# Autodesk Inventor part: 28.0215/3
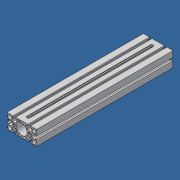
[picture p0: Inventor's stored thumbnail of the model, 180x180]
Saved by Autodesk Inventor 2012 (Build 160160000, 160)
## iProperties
Created: 2011-05
Part Number: 28.0215/3
Material: Aluminum-6061
Description: L = TRAVEL + 4.331", MILL TO 28.0215/3
Document SubType Name: Modeling
Designer: Administrator
Stock Number: 20.1017 PROFILE 45X90 S
Density: 2.71 g/cm^3
Vendor: F
FINISH: CLEAR ANODIZED
Author: Administrator
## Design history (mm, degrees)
sketch "Sketch1"
  geometry: L1 (11.7, 20.5)-(11.7, 15.701) reference; L2 (-11.7, 15.701)-(-11.7, 20.5) reference; L3 (-11.7, 20.5)-(11.7, 20.5) reference; L4 (-11.7, -20.5)-(-11.7, -15.701) reference; L5 (11.7, -15.701)-(11.7, -20.5) reference; L6 (11.7, -20.5)-(-11.7, -20.5) reference; L7 (26.6, 22.5)-(26.6, 18) reference; L8 (27.1, 18)-(29.3, 18) reference; L9 (29.3, 18)-(29.3, 9.5) reference; L10 (29.3, 9.5)-(27, 7.2) reference; L11 (27, 7.2)-(18, 7.2) reference; L12 (18, 7.2)-(15.7, 9.5) reference; L13 (15.7, 9.5)-(15.7, 18) reference; L14 (18.4, 18)-(18.4, 22.5) reference; L15 (-18.4, 22.5)-(-18.4, 18) reference; L16 (-15.7, 18)-(-15.7, 9.5) reference; L17 (-15.7, 9.5)-(-18, 7.2) reference; L18 (-18, 7.2)-(-27, 7.2) reference; L19 (-27, 7.2)-(-29.3, 9.5) reference; L20 (-29.3, 9.5)-(-29.3, 18) reference; L21 (-29.3, 18)-(-27.1, 18) reference; L22 (-26.6, 18)-(-26.6, 22.5) reference; L23 (-45, 4.1)-(-40.5, 4.1) reference; L24 (-40.5, 6.8)-(-32, 6.8) reference; L25 (-32, 6.8)-(-29.7, 4.5) reference; L26 (-29.7, 4.5)-(-29.7, -4.5) reference; L27 (-29.7, -4.5)-(-32, -6.8) reference; L28 (-32, -6.8)-(-40.5, -6.8) reference; L29 (-40.5, -6.8)-(-40.5, -4.6) reference; L30 (-40.5, -4.1)-(-45, -4.1) reference; L31 (-45, -22.5)-(-45, -4.4) reference; L32 (-26.6, -22.5)-(-26.6, -18) reference; L33 (-27.1, -18)-(-29.3, -18) reference; L34 (-29.3, -18)-(-29.3, -9.5) reference; L35 (-29.3, -9.5)-(-27, -7.2) reference; L36 (-27, -7.2)-(-18, -7.2) reference; L37 (-18, -7.2)-(-15.7, -9.5) reference; L38 (-15.7, -9.5)-(-15.7, -18) reference; L39 (-18.4, -18)-(-18.4, -22.5) reference; L40 (18.4, -22.5)-(18.4, -18) reference; L41 (15.7, -18)-(15.7, -9.5) reference; L42 (15.7, -9.5)-(18, -7.2) reference; L43 (18, -7.2)-(27, -7.2) reference; L44 (27, -7.2)-(29.3, -9.5) reference; L45 (29.3, -9.5)-(29.3, -18) reference; L46 (29.3, -18)-(27.1, -18) reference; L47 (26.6, -18)-(26.6, -22.5) reference; L48 (45, -22.5)-(26.9, -22.5) reference; L49 (45, -4.4)-(45, -22.5) reference; L50 (45, -4.1)-(40.5, -4.1) reference; L51 (40.5, -4.6)-(40.5, -6.8) reference; L52 (40.5, -6.8)-(32, -6.8) reference; L53 (32, -6.8)-(29.7, -4.5) reference; L54 (29.7, -4.5)-(29.7, 4.5) reference; L55 (29.7, 4.5)-(32, 6.8) reference; L56 (32, 6.8)-(40.5, 6.8) reference; L57 (40.5, 4.1)-(45, 4.1) reference; L58 (26.9, 22.5)-(45, 22.5) reference; L59 (-45, -4.4)-(-45, -4.1) reference; L60 (-45, 4.1)-(-45, 22.5) reference; L61 (-40.5, -4.6)-(-40.5, -4.1) reference; L62 (-40.5, 4.1)-(-40.5, 6.8) reference; L63 (-27.1, 18)-(-26.6, 18) reference; L64 (-18.4, 18)-(-15.7, 18) reference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; C1 r 3.75 at (22.5, 0) reference; C2 r 3.75 at (-22.5, 0) reference; C3 r 16 at (0, 0) reference; C4 r 5.85 at (-37.15, -14.65) reference; C5 r 5.85 at (-37.15, 14.65) reference; C6 r 5.85 at (37.15, -14.65) reference; C7 r 5.85 at (37.15, 14.65) reference; A1 r 1 centre (10.7, 15.701) between (10.137, 14.874) and (11.7, 15.701) reference; A2 r 18 centre (0, 0) between (10.137, 14.874) and (-10.137, 14.874) reference; A3 r 1 centre (-10.7, 15.701) between (-11.7, 15.701) and (-10.137, 14.874) reference; A4 r 1 centre (-10.7, -15.701) between (-10.137, -14.874) and (-11.7, -15.701) reference; A5 r 18 centre (0, 0) between (-10.137, -14.874) and (10.137, -14.874) reference; A6 r 1 centre (10.7, -15.701) between (11.7, -15.701) and (10.137, -14.874) reference
  constraints: 164 end point, 36 horizontal, 34 vertical, 13 centre point, 12 point on circle, 126 other
extrude "Extrusion1" new body sketch "Sketch1" stored distance "d0" = 414.8 (computed from TRAVEL); taper "d1" = 0 deg
sketch "Sketch2"
  geometry: L1 (0, 0)-(36.8, 0) reference; L2 (36.8, 414.8)-(0, 414.8) reference; L3 (0, 0)-(0, 414.8) reference; L4 (13.65, 394.8)-(13.65, 20); L5 (23.15, 20)-(23.15, 394.8); A1 r 4.75 centre (18.4, 394.8) between (23.15, 394.8) and (13.65, 394.8); A2 r 4.75 centre (18.4, 20) between (13.65, 20) and (23.15, 20); 3 further points
  constraints: 4 end point, 4 point on circle, 4 tangent, 2 centre point, 2 midpoint, 2 vertical alignment, 1 parallel
  dimensions: "d2" = 4.75 radius of A1; "d3" = 20 distance from line of A1.centre L2; "d4" = 20 distance from line of L1 A2.centre (= d3)
extrude "Extrusion2" cut sketch "Sketch2" distance "d5" = 12.7; taper "d6" = 0 deg
thread "Thread1" dims "d7" = 25.4, "d8" = 0
thread "Thread2" dims "d9" = 25.4, "d10" = 0
thread "Thread3" dims "d11" = 25.4, "d12" = 0
thread "Thread5" dims "d15" = 25.4, "d16" = 389.4074
body "Solid1"
other parameters: "TRAVEL" = 304.8 [user parameter; used in 1 equation term]
